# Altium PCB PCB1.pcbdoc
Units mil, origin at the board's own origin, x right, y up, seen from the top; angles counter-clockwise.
Board outline 4420.1 x 3302.08 mil, 2 copper layers (Top Layer, Bottom Layer); 26 components, 21 nets, 128 pads, 8 vias.
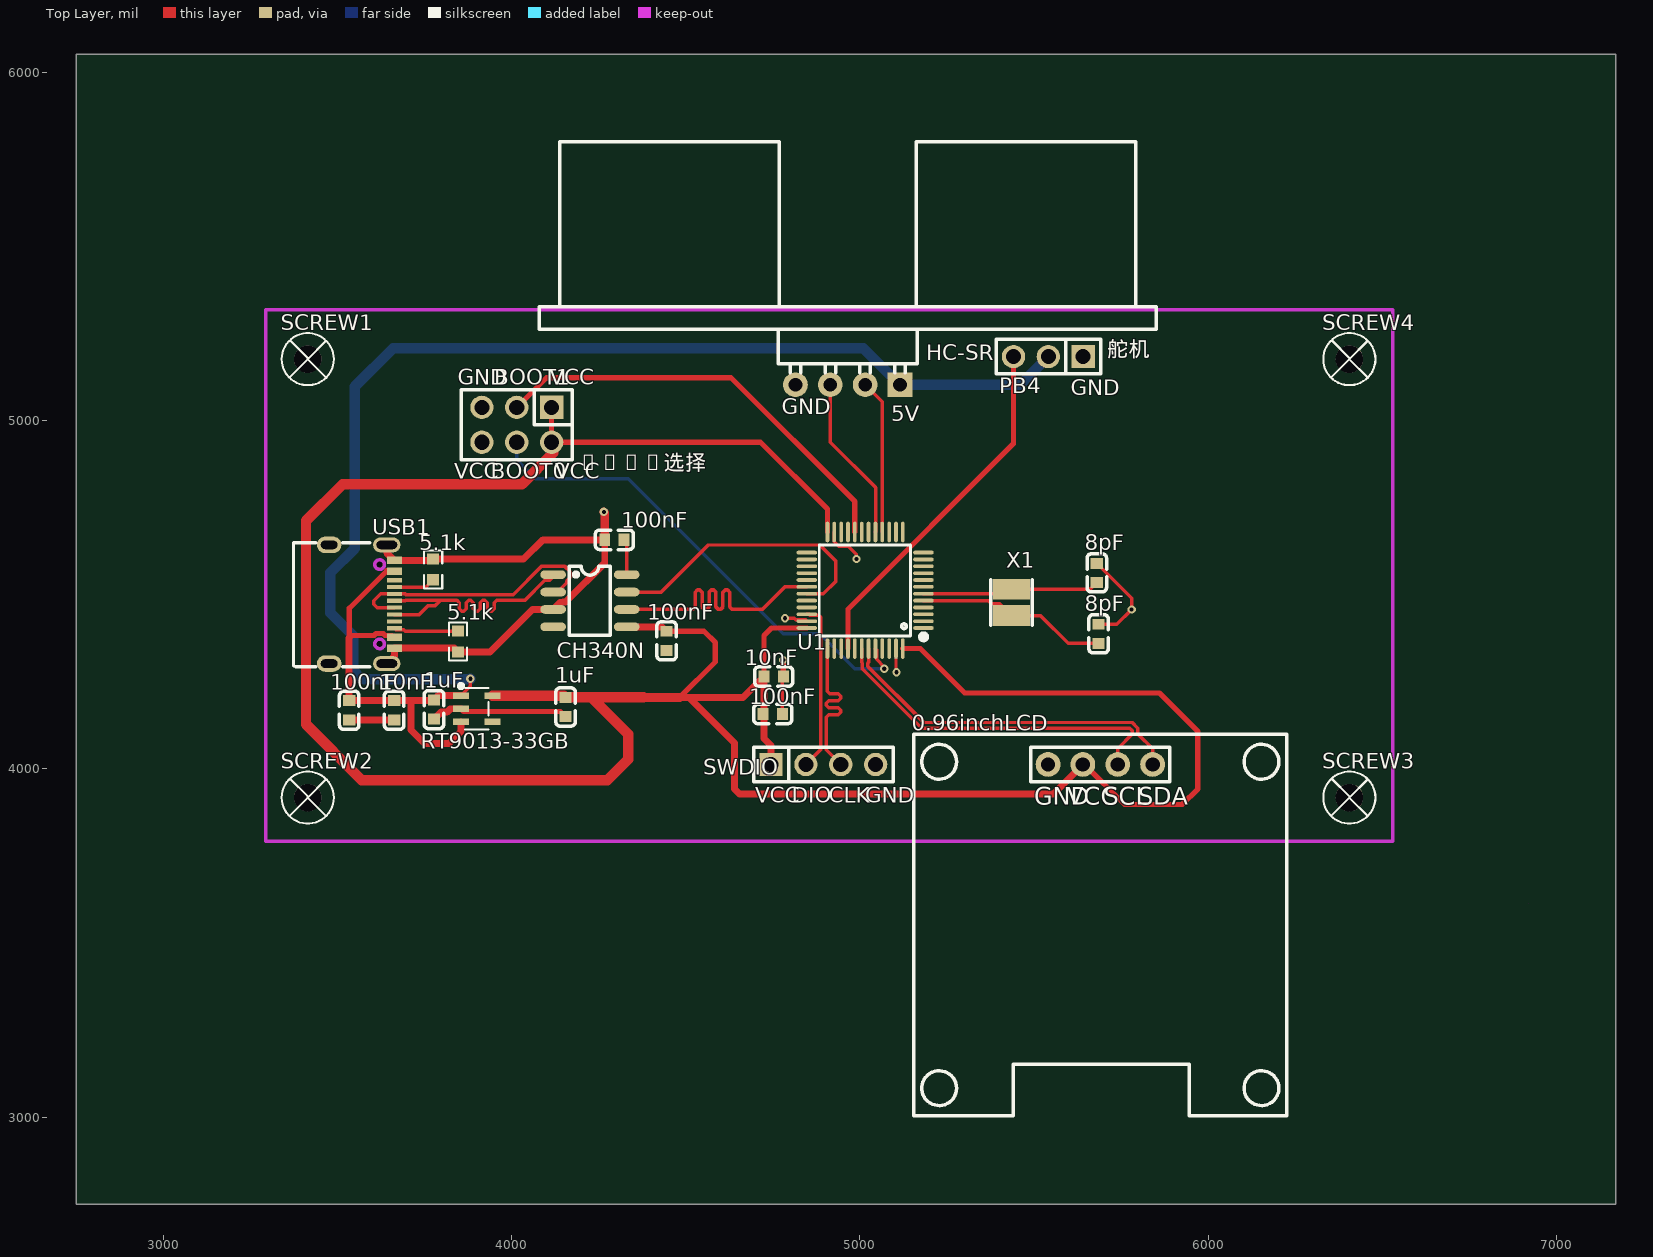
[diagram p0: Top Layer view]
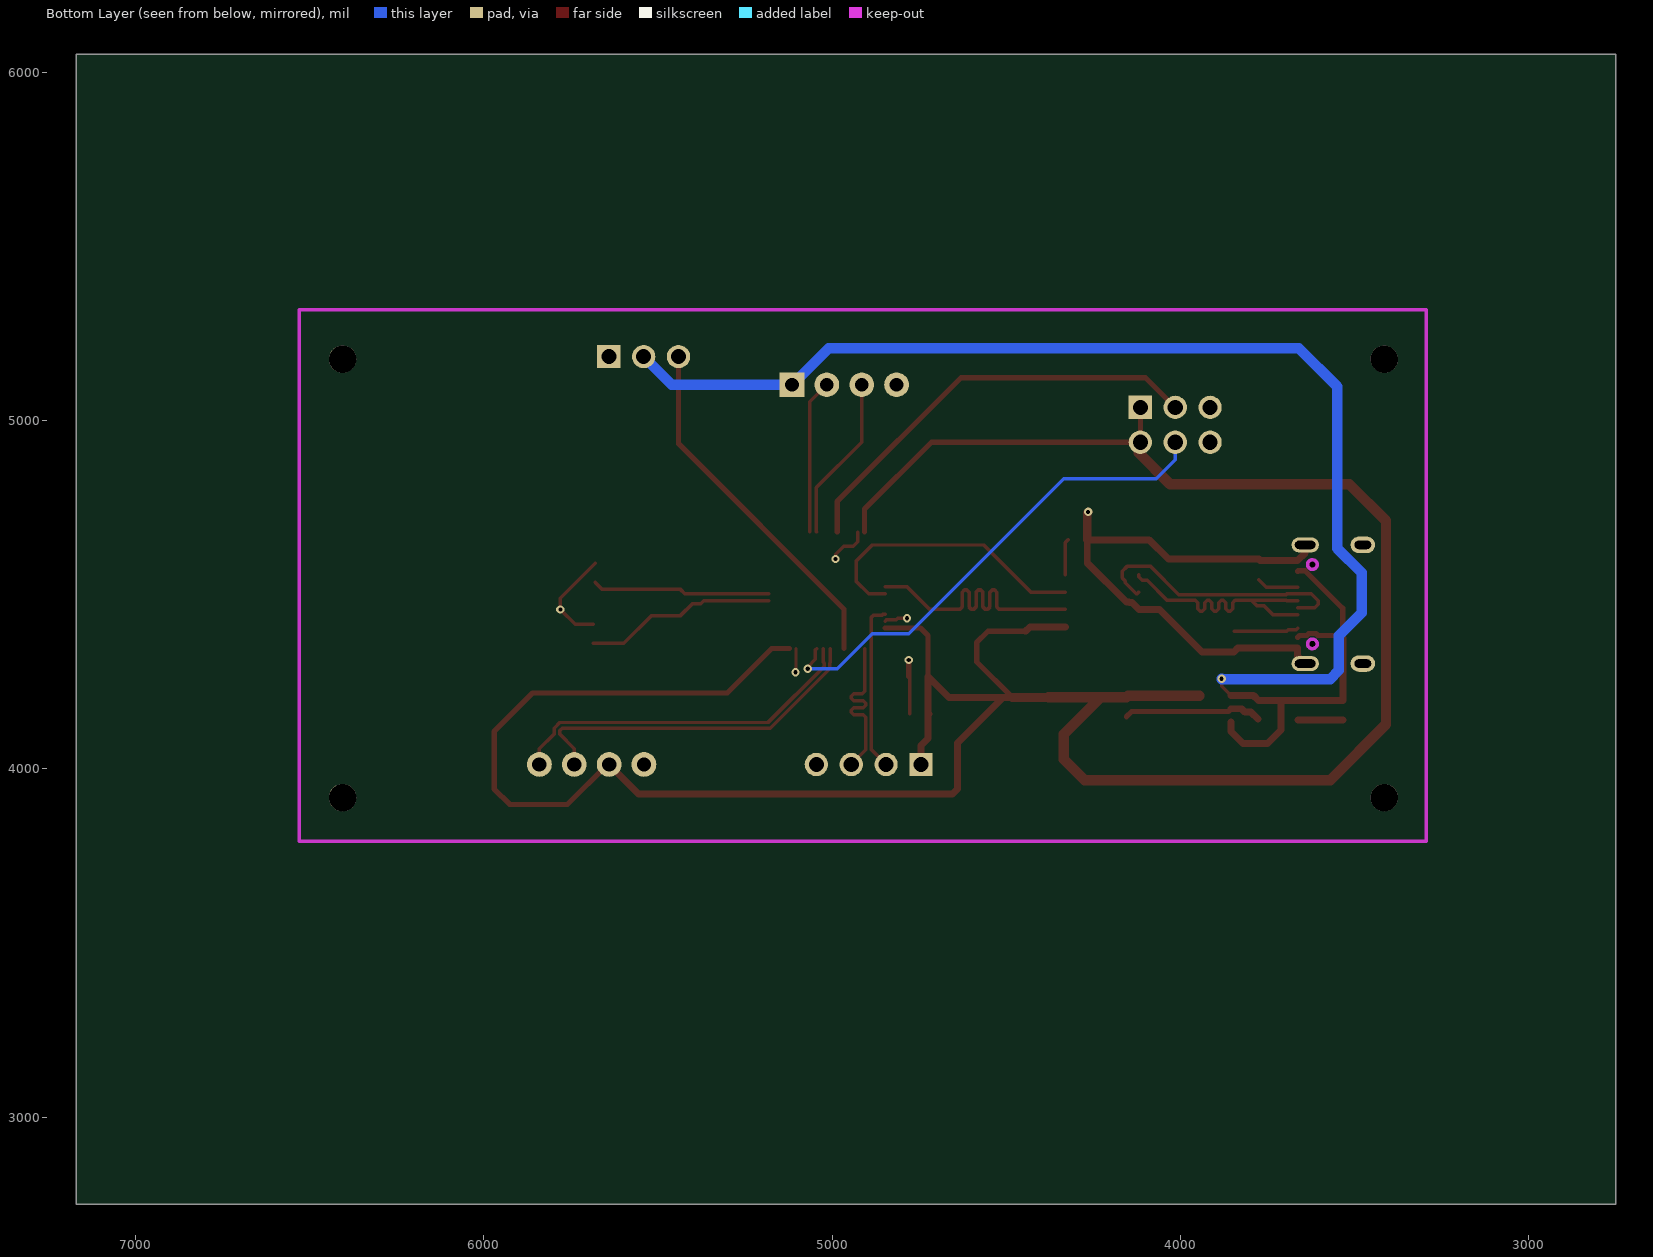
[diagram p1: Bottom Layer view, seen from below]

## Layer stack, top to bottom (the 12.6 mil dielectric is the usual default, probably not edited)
Top Layer: signal copper (thickness not stored)
Dielectric: dielectric 12.6, FR-4, Dk 4.8
Bottom Layer: signal copper (thickness not stored)

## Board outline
7170.1,2750 2750,2750 2750,6052.08 7170.1,6052.08

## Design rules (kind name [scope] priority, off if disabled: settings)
BoardOutlineClearance copperThickness1oz [All] p0: genericclearance=10 ignorepadtopadclearanceinfootprint=FALSE except(0: Arc-SplitContinuation Track-SplitContinuation SMDPad-SplitContinuation THPad-SplitContinuation Via-SplitContinuation Fill-SplitContinuation Poly-SplitContinuation Region-SplitContinuation Text-SplitContinuation; 6: Track-CutoutEdge SMDPad-CutoutEdge THPad-CutoutEdge Via-CutoutEdge Region-CutoutEdge; 11.8: Track-OutlineEdge SMDPad-OutlineEdge THPad-OutlineEdge Via-OutlineEdge Fill-OutlineEdge Region-OutlineEdge Poly-OutlineEdge Text-OutlineEdge Fill-CutoutEdge)
BoardOutlineClearance copperThickness2oz [All] p0: genericclearance=10 ignorepadtopadclearanceinfootprint=FALSE except(0: Arc-SplitContinuation Track-SplitContinuation SMDPad-SplitContinuation THPad-SplitContinuation Via-SplitContinuation Fill-SplitContinuation Poly-SplitContinuation Region-SplitContinuation Text-SplitContinuation; 6: Track-CutoutEdge SMDPad-CutoutEdge THPad-CutoutEdge Via-CutoutEdge Region-CutoutEdge; 11.8: Track-OutlineEdge SMDPad-OutlineEdge THPad-OutlineEdge Via-OutlineEdge Fill-OutlineEdge Region-OutlineEdge Poly-OutlineEdge Text-OutlineEdge Fill-CutoutEdge)
Clearance copperThickness1oz [(InNet('GND') OR InNet('OSCIN') OR InNet('OSCOUT') OR InNet('VCC') OR InNet('$1N2475') OR InNet('+5V') OR InNet('BOOT1') OR InNet('BOOT0') OR InNet('PB4') OR InNet('SWDIO') OR InNet('SWCLK') OR InNet('$1N1810') OR InNet('$1N1822') OR InNet('TRIG') OR InNet('ECHO') OR InNet('TX') OR InNet('RX') OR InNet('SCL') OR InNet('SDA') OR InNet('D+') OR InNet('D-'))] p1: gap=7 ignorepadtopadclearanceinfootprint=FALSE except(4: Track-Track; 6: Track-SMDPad SMDPad-SMDPad Track-THPad SMDPad-THPad THPad-THPad Track-Via SMDPad-Via THPad-Via Via-Via SMDPad-Fill THPad-Fill Via-Fill Fill-Fill Track-Region SMDPad-Region THPad-Region Via-Region Region-Region Track-Poly SMDPad-Poly THPad-Poly Via-Poly Fill-Poly Region-Poly Poly-Poly Track-Text SMDPad-Text THPad-Text Via-Text Fill-Text Region-Text Poly-Text Text-Text; 6.9: Track-Hole SMDPad-Hole THPad-Hole Via-Hole Fill-Hole Region-Hole Poly-Hole Text-Hole Sheet-Hole; 11.8: Track-Fill Fill-Region Track-Sheet SMDPad-Sheet THPad-Sheet Via-Sheet Fill-Sheet Region-Sheet Poly-Sheet Text-Sheet)
Clearance copperThickness2oz [All] p1: gap=7 ignorepadtopadclearanceinfootprint=FALSE except(6: Track-SMDPad SMDPad-SMDPad Track-THPad SMDPad-THPad THPad-THPad Track-Via SMDPad-Via THPad-Via Via-Via SMDPad-Fill THPad-Fill Via-Fill Fill-Fill Track-Region SMDPad-Region THPad-Region Via-Region Region-Region Track-Poly SMDPad-Poly THPad-Poly Via-Poly Fill-Poly Region-Poly Poly-Poly Track-Text SMDPad-Text THPad-Text Via-Text Fill-Text Region-Text Poly-Text Text-Text; 6.9: Track-Hole SMDPad-Hole THPad-Hole Via-Hole Fill-Hole Region-Hole Poly-Hole Text-Hole Sheet-Hole; 8: Track-Track; 11.8: Track-Fill Fill-Region Track-Sheet SMDPad-Sheet THPad-Sheet Via-Sheet Fill-Sheet Region-Sheet Poly-Sheet Text-Sheet)
DiffPairsRouting differentialPair [All] p1: maxuncoupledlength=10 minlimit=6 maxlimit=6 mostfreqgap=6 toplayer_minwidth=5 toplayer_prefwidth=10 toplayer_maxwidth=100 bottomlayer_minwidth=5 bottomlayer_prefwidth=10 bottomlayer_maxwidth=100
PasteMaskExpansion pasteMaskExpansion [All] p1: expansion=0
PlaneConnect innerPlane [All] p1: planeconnectstyle=Relief reliefexpansion=20 reliefentries=4 reliefconductorwidth=10 reliefairgap=10
PolygonConnect copperRegion [All] p1: connectstyle=Relief reliefentries=4 reliefconductorwidth=10 polygonreliefangle="90 Angle" airgapwidth=10
RoutingVias viaSize [All] p1: viastyle="Through Hole" holewidth=12.0078 minholewidth=11.811 maxholewidth=248.0314 width=24.0158 minwidth=19.685 maxwidth=393.7008
SolderMaskExpansion solderMaskExpansion [All] p1: useseparateexpansions=TRUE expansion=2 expansionbottom=2
Width copperThickness1oz [All] p1: maxlimit=100 minlimit=5 preferedwidth=10
Width copperThickness2oz [All] p1: maxlimit=100 minlimit=8 preferedwidth=10

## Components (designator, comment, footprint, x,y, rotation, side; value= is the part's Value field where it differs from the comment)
0.96inchLCD "HS96L03W2C03" OLED-TH_L27.8-W27.2-P2.54_C9900033791 5690,4012.87 r0 top
1uF "CAP_0603" C0603 3777.44,4170.43 r90 top
1uF "CAP_0603" C0603 4155,4177.87 r90 top
5.1k "Res_0603" R0603 3846.3,4365.8 r270 top
5.1k "Res_0603" R0603 3775,4572.87 r90 top
8pF "CAP_0603" C0603 5685,4387.87 r90 top
8pF "CAP_0603" C0603 5680,4562.87 r90 top
10nF "CAP_0603" C0603 3663.07,4168.5 r90 top
10nF "CAP_0603" C0603 4752.44,4265.31 r180 top
100nF "CAP_0603" C0603 4445,4367.75 r90 top
100nF "CAP_0603" C0603 4295.12,4657.87 r180 top
100nF "CAP_0603" C0603 3534.06,4168.38 r90 top
100nF "CAP_0603" C0603 4750,4157.87 r180 top
boot选择 "PZ254V-12-6P" HDR-TH_6P-P2.54-V-M-R2-C3-S2.54 4015,4987.87 r180 top
CH340N "CH340N" SOP-8_L4.9-W3.9-P1.27-LS6.0-BL 4225,4482.87 r270 top
HC-SR "HC-SR04" TH_HC-SR04V 4965,5102.87 r180 top
RT9013-33GB "RT9013-33GB" SOT-23-5_L3.0-W1.7-P0.95-LS2.8-BL 3900,4172.87 r270 top
SCREW1 "M2螺丝" M2螺丝 3415,5176.3 r0 top
SCREW2 "M2螺丝" M2螺丝 3415,3917.87 r0 top
SCREW3 "M2螺丝" M2螺丝 6405,3917.87 r0 top
SCREW4 "M2螺丝" M2螺丝 6405,5176.3 r0 top
SWDIO "HC-PZ254-11.5L-1x4PZ" HDR-TH_4P-P2.54-V-M 4895,4012.87 r0 top
U1 "STM32F103C8T6" LQFP-48_L7.0-W7.0-P0.50-LS9.0-BL 5015,4512.87 r90 top
USB1 "TYPE-C 16PIN 2MD(073)" USB-C-SMD_TYPE-C-6PIN-2MD-073 3570,4472.87 r270 top
X1 "NX3225GD-8MHZ-STD-CRA-3" OSC-SMD_2P-L3.2-W2.5 5435,4477.87 r90 top
舵机 "PZ254V-11-03P" HDR-TH_3P-P2.54-V-M 5540.9,5183.71 r180 top

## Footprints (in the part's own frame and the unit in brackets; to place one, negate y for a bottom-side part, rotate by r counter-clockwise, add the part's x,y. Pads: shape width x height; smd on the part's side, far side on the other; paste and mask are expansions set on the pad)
C0603 [mm]
  rect 0.8x0.9 smd: 1(-0.7,0) 2(0.7,0)
  silkscreen extent -1.39,-0.71 1.39,0.71
HDR-TH_3P-P2.54-V-M [mm]
  rect 1.7x1.7 hole 1.1: 1(-2.54,0)
  round 1.7 hole 1.1: 2(0,0) 3(2.54,0)
  silkscreen extent -3.81,-1.25 3.81,1.25
HDR-TH_4P-P2.54-V-M [mm]
  rect 1.7x1.7 hole 1.1: 1(-3.81,0)
  round 1.7 hole 1.1: 2(-1.27,0) 3(1.27,0) 4(3.81,0)
  silkscreen extent -5.08,-1.27 5.08,1.27
HDR-TH_6P-P2.54-V-M-R2-C3-S2.54 [mm]
  rect 1.7x1.7 hole 1.1: 1(-2.54,-1.27)
  round 1.7 hole 1.1: 2(-2.54,1.27) 3(0,-1.27) 4(0,1.27) 5(2.54,-1.27) 6(2.54,1.27)
  silkscreen extent -4.04,-2.54 4.04,2.54
LQFP-48_L7.0-W7.0-P0.50-LS9.0-BL [mm]
  oval 0.27x1.5 smd: 1(-2.75,-4.25) 2(-2.25,-4.25) 3(-1.75,-4.25) 4(-1.25,-4.25) 5(-0.75,-4.25) 6(-0.25,-4.25) 7(0.25,-4.25) 8(0.75,-4.25) 9(1.25,-4.25) 10(1.75,-4.25) 11(2.25,-4.25) 12(2.75,-4.25) 25(2.75,4.25) 26(2.25,4.25) 27(1.75,4.25) 28(1.25,4.25) 29(0.75,4.25) 30(0.25,4.25) 31(-0.25,4.25) 32(-0.75,4.25) 33(-1.25,4.25) 34(-1.75,4.25) 35(-2.25,4.25) 36(-2.75,4.25)
  oval 1.5x0.27 smd: 13(4.25,-2.75) 14(4.25,-2.25) 15(4.25,-1.75) 16(4.25,-1.25) 17(4.25,-0.75) 18(4.25,-0.25) 19(4.25,0.25) 20(4.25,0.75) 21(4.25,1.25) 22(4.25,1.75) 23(4.25,2.25) 24(4.25,2.75) 37(-4.25,2.75) 38(-4.25,2.25) 39(-4.25,1.75) 40(-4.25,1.25) 41(-4.25,0.75) 42(-4.25,0.25) 43(-4.25,-0.25) 44(-4.25,-0.75) 45(-4.25,-1.25) 46(-4.25,-1.75) 47(-4.25,-2.25) 48(-4.25,-2.75)
  silkscreen extent -3.59,-4.46 3.3,3.34
M2螺丝 [mm]
  round 2 hole 2: 1(0,0)
  silkscreen extent -1.9,-1.9 1.9,1.9
OLED-TH_L27.8-W27.2-P2.54_C9900033791 [mm]
  round 1.8 hole 1.05: 1(-3.81,0) 2(-1.27,0) 3(1.27,0) 4(3.81,0)
  silkscreen extent -13.6,-25.6 13.6,2.2
OSC-SMD_2P-L3.2-W2.5 [mm]
  rect 1.5x2.7 smd: 1(0.95,0) 2(-0.95,0)
  silkscreen extent -1.65,-1.52 1.65,1.52
R0603 [mil]
  rect 31.75x34.02 smd: 1(-29.66,0) 2(29.66,0)
  silkscreen extent -55,-26 55,26
SOP-8_L4.9-W3.9-P1.27-LS6.0-BL [mm]
  oval 0.63x1.865 smd: 1(-1.905,-2.682) 2(-0.635,-2.682) 3(0.635,-2.682) 4(1.905,-2.682) 5(1.905,2.682) 6(0.635,2.682) 7(-0.635,2.682) 8(-1.905,2.682)
  silkscreen extent -2.5,-1.5 2.5,1.48
SOT-23-5_L3.0-W1.7-P0.95-LS2.8-BL [mm]
  rect 0.49x1.157 smd: 1(-0.95,-1.154) 2(0,-1.154) 3(0.95,-1.154)
  rect 0.49x1.175 smd: 4(0.95,1.154) 5(-0.95,1.154)
  silkscreen extent -1.8,-1.29 1.53,0.85
TH_HC-SR04V [mm]
  rect 1.8x1.8 hole 1.001: 1(-3.81,0)
  round 1.8 hole 1.001: 2(-1.27,0) 3(1.27,0) 4(3.81,0)
  silkscreen extent -22.5,-17.7 22.5,-0.89
USB-C-SMD_TYPE-C-6PIN-2MD-073 [mm]
  rect 0.55x1.1 smd: 1(-3.2,2.375) 2(-2.4,2.375) 11(2.4,2.375) 12(3.2,2.375)
  rect 0.3x1.1 smd: 3(-1.75,2.375) 4(-1.25,2.375) 5(-0.75,2.375) 6(-0.25,2.375) 7(0.25,2.375) 8(0.75,2.375) 9(1.25,2.375) 10(1.75,2.375)
  oval 1.2x1.8 hole 0.6 slot 1.2 at 90 deg: 13(-4.325,-2.375) 14(4.325,-2.375)
  oval 1.1x2 hole 0.6 slot 1.5 at 90 deg: 13(-4.325,1.825) 14(4.325,1.825)
  Board Outline Layer circle w0.005: c-2.89,1.305 r0.35
  Board Outline Layer circle w0.005: c2.89,1.305 r0.35
  Board Outline Layer circle w0.254: c-2.89,1.305 r0.35
  Board Outline Layer circle w0.254: c2.89,1.305 r0.35
  Multi-Layer board cut-out: -2.89,1.655 -3.062,1.606 -3.187,1.478 -3.233,1.305 -3.187,1.132 -3.062,1.004 -2.89,0.955 -2.89,0.955 -2.718,1.004 -2.592,1.132 -2.547,1.305 -2.592,1.478 -2.718,1.606 -2.89,1.655
  Multi-Layer board cut-out: 2.89,1.655 2.718,1.606 2.593,1.478 2.547,1.305 2.593,1.132 2.718,1.004 2.89,0.955 2.89,0.955 3.062,1.004 3.188,1.132 3.233,1.305 3.188,1.478 3.062,1.606 2.89,1.655
  silkscreen extent -4.5,-4.97 4.57,0.6

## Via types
v1: diameter 24.02, hole 12.01, Top Layer to Bottom Layer, 8 vias

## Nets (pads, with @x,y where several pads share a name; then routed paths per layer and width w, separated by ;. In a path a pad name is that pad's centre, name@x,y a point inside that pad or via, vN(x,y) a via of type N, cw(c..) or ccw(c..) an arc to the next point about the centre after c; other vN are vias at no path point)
$1N1810: 5.1k.1@3846.3,4395.46 USB1.10 | length 186.3
  Top Layer w10: USB1.10 3667.28,4400.19 3689.71,4400.19 3694.43,4395.46 5.1k.1@3846.3,4395.46
$1N1822: 5.1k.1@3775,4543.21 USB1.4 | length 120.2
  Top Layer w10: USB1.4 3753.86,4522.08 5.1k.1@3775,4543.21
$1N2475: 100nF.1@4322.68,4657.87 CH340N.8 | length 103.3
  Top Layer w10: 100nF.1@4322.68,4657.87 4330.61,4649.94 CH340N.8
+5V: 1uF.2@3777.44,4197.99 10nF.2@3663.07,4196.06 100nF.2@3534.06,4195.94 HC-SR.1 RT9013-33GB.1 RT9013-33GB.3 USB1.2 USB1.11 舵机.2 | length 4582.8
  Top Layer w10: RT9013-33GB.1 3881.85,4237.55 v1(3881.85,4258.82)
  Top Layer w15: 3534.06,4375.86 3534.34,4376.14 ; USB1.11 3658.51,4383.38 3637.11,4383.38 3631.63,4388.85 3611.12,4388.85 3605.64,4383.38 3541.58,4383.38 3534.34,4376.14 ; USB1.2 3662.13,4568.73 3642.02,4568.73 3534.34,4461.05 3534.34,4376.14
  Top Layer w20: 3534.06,4375.86 3534.06,4195.94 3662.95,4195.94 3663.07,4196.06 3711.15,4196.06 ; RT9013-33GB.3 3854.58,4107.45 3820,4072.87 3750,4072.87 3711.15,4111.72 3711.15,4196.06 ; RT9013-33GB.1 3789.72,4210.27 3777.44,4197.99 3775.51,4196.06 3711.15,4196.06
  Bottom Layer w30: v1(3881.85,4258.82) 3880.91,4257.87 3570,4257.87 3545,4282.87 3545,4382.87 3480,4447.87 3480,4562.87 3550,4632.87 3550,5097.87 3660,5207.87 5010,5207.87 HC-SR.1 5460.06,5102.87 舵机.2
BOOT0: boot选择.4 U1.44 | length 1421.8
  Top Layer w10: U1.44 5047.91,4342.17 5047.91,4314.59 5070,4292.5 v1(5070,4287.87)
  Bottom Layer w10: boot选择.4 4015,4887.87 4070,4832.87 4335,4832.87 4780,4387.87 4885,4387.87 4985,4287.87 v1(5070,4287.87)
BOOT1: boot选择.3 U1.20 | length 1240.1
  Top Layer w15: boot选择.3 4100,5122.87 4630,5122.87 4985.47,4767.4 U1.20
D+: CH340N.1 USB1.6 USB1.8 | length 780.4
  Top Layer w10: USB1.8 3735.47,4443.35 3760,4467.87 3780,4467.87 3793.98,4481.85 3793.98,4484.56 ; USB1.6 3695.16,4482.72 3697,4484.56 3793.98,4484.56 ; CH340N.1 4119.39,4551.24 4109.57,4541.43 4095.56,4541.43 4038.69,4484.56 3957.44,4484.56 3950.37,4477.49 3950.37,4459.94 3943.3,4452.87 3937.44,4452.87 3930.37,4459.94 3930.37,4477.49 3923.3,4484.56 3917.44,4484.56 3910.37,4477.49 3910.37,4459.94 3903.3,4452.87 3897.44,4452.87 3890.37,4459.94 3890.37,4477.49 3883.3,4484.56 3877.44,4484.56 3870.37,4477.49 3870.37,4459.94 3863.3,4452.87 3857.44,4452.87 3850.37,4459.94 3850.37,4477.49 3843.3,4484.56 3793.98,4484.56
D-: CH340N.2 USB1.5 USB1.7 | length 773.4
  Top Layer w10: USB1.7 3614.84,4463.03 3605,4472.87 3605,4482.87 3624.53,4502.4 USB1.5 3695.16,4502.4 3697,4500.56 4004.69,4500.56 4085.39,4581.26 4153.39,4581.26 4167.09,4567.56 4167.09,4548.19 4158.46,4539.56 4158.46,4534.8 4126.46,4502.8 4124.46,4502.8 CH340N.2
ECHO: HC-SR.3 U1.17 | length 476.7
  Top Layer w10: HC-SR.3 4915,4937.87 5045,4807.87 5045,4680.66 U1.17
GND: 0.96inchLCD.1 1uF.1 5.1k.2 8pF.2 10nF.1 100nF.1@3534.06,4140.82 100nF.1@4445,4340.19 100nF.1@4777.56,4157.87 100nF.2@4267.56,4657.87 boot选择.5 boot选择.6 CH340N.3 HC-SR.4 RT9013-33GB.2 SWDIO.4 U1.23 U1.35 U1.47 USB1.1 USB1.12 USB1.13 USB1.14 舵机.1 | length 2822
  Top Layer w10: 100nF.1@4777.56,4157.87 4777.56,4262.87 10nF.1@4780,4265.31 ; v1(4785,4432.87) 4811.52,4432.87 4816.72,4427.67 4844.3,4427.67 U1.35 ; U1.23 4926.42,4652.61 4939.35,4639.68 4966.93,4639.68 4990,4616.61 v1(4990,4602.87) ; U1.47 5103.58,4279.29 v1(5105,4277.87) ; 8pF.2@5680,4590.43 5780,4490.43 v1(5780,4457.87) 5737.56,4415.43 8pF.2@5685,4415.43
  Top Layer w15: RT9013-33GB.2 3862.26,4165.19 4140,4165.19 1uF.1@4155,4150.19 ; 10nF.1@4780,4265.31 v1(4780,4312.87)
  Top Layer w20: 100nF.1@3534.06,4140.82 3662.95,4140.82 10nF.1@3663.07,4140.94 ; USB1.14@3641.86,4302.6 3663.51,4324.25 USB1.12 3835.56,4346.89 3846.3,4336.14 3938.27,4336.14 4060,4457.87 CH340N.3 4139.39,4477.87 4146.77,4477.87 4148.39,4479.49 4155.46,4479.49 4267.56,4591.59 4267.56,4657.87 4090,4657.87 4034.66,4602.53 3775,4602.53 3771.32,4598.86 USB1.1 3641.86,4620.51 USB1.13@3641.86,4643.15 ; 1uF.1@3777.44,4142.87 3797.44,4162.87 3815,4162.87 3825,4172.87 RT9013-33GB.2
  Top Layer w25: v1(4265,4737.87) 4267.56,4735.31 100nF.2@4267.56,4657.87
OSCIN: 8pF.1@5685,4360.31 U1.5 X1.2 | length 553.6
  Top Layer w10: U1.5 5368.72,4483.34 5377.3,4474.76 5400.71,4474.76 X1.2 5517.4,4440.47 5597.56,4360.31 8pF.1@5685,4360.31
OSCOUT: 8pF.1@5680,4535.31 U1.6 X1.1 | length 511.1
  Top Layer w10: U1.6 5422.76,4503.03 X1.1 5659.96,4515.27 8pF.1@5680,4535.31
PB4: U1.40 舵机.3 | length 1035
  Top Layer w15: U1.40 4965.79,4458.66 5440.9,4933.77 舵机.3
RX: CH340N.7 U1.31 | length 830.7
  Top Layer w10: CH340N.7 4430,4507.87 4565,4642.87 4885,4642.87 4930,4597.87 4930,4537.87 4895.16,4503.03 U1.31
SCL: 0.96inchLCD.3 U1.42 | length 1022
  Top Layer w10: U1.42 5005.16,4306.02 5007,4304.18 5007,4287.56 5177.18,4117.38 5774.93,4117.38 5782,4110.31 5782,4100.31 5740,4058.3 0.96inchLCD.3
SDA: 0.96inchLCD.4 U1.43 | length 1022
  Top Layer w10: U1.43 5024.84,4306.02 5023,4304.18 5023,4294.18 5183.81,4133.38 5781.56,4133.38 5798,4116.93 5798,4100.31 5840,4058.3 0.96inchLCD.4
SWCLK: SWDIO.3 U1.37 | length 481.2
  Top Layer w10: U1.37 4906.73,4222.66 4913.8,4215.59 4937.93,4215.59 4945,4208.51 4945,4202.66 4937.93,4195.59 4910.07,4195.59 4903,4188.51 4903,4182.66 4910.07,4175.59 4937.93,4175.59 4945,4168.51 4945,4162.66 4937.93,4155.59 4910.07,4155.59 4903,4148.51 4903,4054.87 SWDIO.3
SWDIO: SWDIO.2 U1.34 | length 484.1
  Top Layer w10: SWDIO.2 4887,4054.87 4887,4396.66 4888.19,4397.85 4888.19,4434.68 4882.28,4440.59 4857.28,4440.59 4853.9,4443.97 U1.34
TRIG: HC-SR.2 U1.16 | length 443.1
  Top Layer w10: HC-SR.2 5064.21,5053.66 U1.16
TX: CH340N.6 U1.30 | length 830.2
  Top Layer w10: CH340N.6 4519.77,4457.87 4526.84,4464.94 4526.84,4506.8 4533.91,4513.87 4539.77,4513.87 4546.84,4506.8 4546.84,4464.94 4553.91,4457.87 4559.77,4457.87 4566.84,4464.94 4566.84,4506.8 4573.91,4513.87 4579.77,4513.87 4586.84,4506.8 4586.84,4464.94 4593.91,4457.87 4599.77,4457.87 4606.84,4464.94 4606.84,4506.8 4613.91,4513.87 4619.77,4513.87 4626.84,4506.8 4626.84,4464.94 4633.91,4457.87 4720,4457.87 4784.84,4522.71 U1.30
VCC: 0.96inchLCD.2 1uF.2@4155,4205.43 10nF.2@4724.88,4265.31 100nF.2@4445,4395.31 100nF.2@4722.44,4157.87 boot选择.1 boot选择.2 CH340N.5 RT9013-33GB.5 SWDIO.1 U1.24 U1.36 U1.48 | length 8331
  Top Layer w15: boot选择.1 boot选择.2 4715,4937.87 4906.73,4746.14 U1.24 ; 100nF.2@4445,4395.31 4552.56,4395.31 4585,4362.87 4585,4307.87 4482.56,4205.43 ; 10nF.2@4724.88,4265.31 4724.88,4382.87 4746.61,4404.6 U1.36 ; U1.48 5173.27,4345.55 5300.95,4217.87 5860,4217.87 5970,4107.87 5970,3942.87 5925,3897.87 5760,3897.87 5645,4012.87 0.96inchLCD.2
  Top Layer w20: CH340N.5 4432.44,4407.87 100nF.2@4445,4395.31 ; 4482.56,4205.43 4509.04,4205.43 ; SWDIO.1 4745,4067.87 4725,4087.87 4725,4155.31 4722.44,4157.87 4724.88,4160.31 4724.88,4265.31 4665,4205.43 4509.04,4205.43 ; 0.96inchLCD.2 5555.86,3928.73 4654.14,3928.73 4640,3942.87 4640,4074.47 4509.04,4205.43
  Top Layer w25: 4377.56,4205.43 4482.56,4205.43
  Top Layer w30: RT9013-33GB.5 1uF.2@4150.04,4210.27 ; boot选择.2 4120,4932.87 4120,4907.87 4030,4817.87 3515,4817.87 3410,4712.87 3410,4127.87 3570,3967.87 4275,3967.87 4335,4027.87 4335,4099.03 4228.6,4205.43 ; 1uF.2@4155,4205.43 4228.6,4205.43 ; 4377.56,4205.43 4228.6,4205.43
pads on no net: CH340N.4 RT9013-33GB.4 SCREW1.1 SCREW2.1 SCREW3.1 SCREW4.1 U1.1 U1.2 U1.3 U1.4 U1.7 U1.8 U1.9 U1.10 U1.11 U1.12 U1.13 U1.14 U1.15 U1.18 U1.19 U1.21 U1.22 U1.25 U1.26 U1.27 U1.28 U1.29 U1.32 U1.33 U1.38 U1.39 U1.41 U1.45 U1.46 USB1.3 USB1.9

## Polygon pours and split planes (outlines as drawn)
GND on Top Layer (solid, remove dead copper, pour order 0): 6920,3612.87 6920.1,3612.87 6920.1,3612.77 6920,3612.77
GND on Top Layer (solid, remove dead copper, pour order 4): 3000,5662.87 6844.55,5662.87 6844.55,3552.24 3000,3552.24
GND on Bottom Layer (solid, remove dead copper, pour order 4): 3175,5387.87 6710,5387.87 6710,3702.87 3175,3702.87

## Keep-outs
Board Outline Layer:
  lines w10: 3295,3792.87 6530,3792.87 6530,5317.87 3295,5317.87 3295,3792.87

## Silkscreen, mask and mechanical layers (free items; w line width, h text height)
Top Silkscreen Layer:
  text "GND" at 3845,5102.87 h45
  text "BOOT1" at 3950,5102.87 h45
  text "VCC" at 4110,5102.87 h45
  text "PB4" at 5400,5077.87 h45
  text "GND" at 5605,5072.87 h45
  text "GND" at 4775,5017.87 h45
  text "5V" at 5090,4997.87 h45
  text "VCC" at 3835,4832.87 h45
  text "BOOT0" at 3940,4832.87 h45
  text "VCC" at 4125,4832.87 h45
  text "VCC" at 4700,3902.87 h45
  text "DIO" at 4805,3902.87 h45
  text "CLK" at 4910,3902.87 h45
  text "GND" at 5015,3902.87 h45
  text "GND" at 5500,3897.87 h50
  text "VCC" at 5595,3897.87 h50
  text "SCL" at 5700,3897.87 h50
  text "SDA" at 5798.64,3897.87 h50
